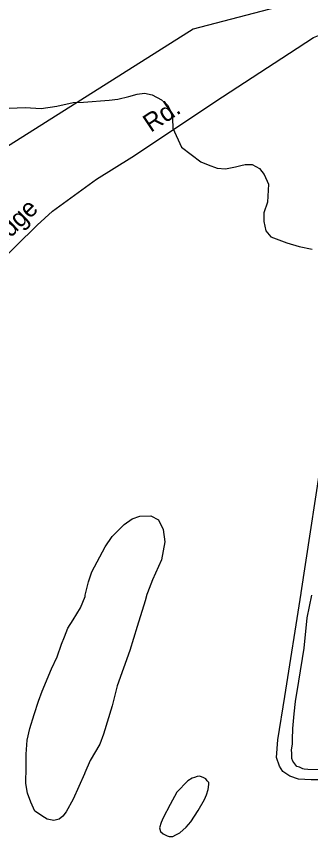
# Model space of a CAD drawing. Extents: x 2206922 to 2357709, y 510027 to 673830.
# Drawn here: x 2263859 to 2265398, y 591384 to 595671 of the extents above; entities that cross this region are included whole.
import ezdxf

# ---------------------------------------------------------------- set-up
doc = ezdxf.new("R2010")
doc.units = 0
for name, color, linetype in [('Exist Hydrographic Misc Water Feature', 7, 'Continuous'), ('Exist Road Non-System Type 51', 7, 'Continuous'), ('Exist Road Secondary Type 51 Attributed', 7, 'Continuous'), ('Exist Road Secondary Type 51 Label', 7, 'Continuous'), ('Exist Utilities Electrical Transmission Line', 7, 'Continuous')]:
    doc.layers.add(name, color=color, linetype=linetype)

msp = doc.modelspace()

# ---------------------------------------------------------------- linework, layer by layer
at = {"layer": 'Exist Hydrographic Misc Water Feature'}
for points in [[(2263820.5, 595191.7), (2263904.2, 595194.5), (2263988.5, 595189.5), (2264070.5, 595202.3), (2264156, 595221), (2264209.9, 595223.4), (2264343.6, 595232.5), (2264389.7, 595238.9), (2264447.6, 595251.7), (2264491.2, 595264.1), (2264529.2, 595270.2), (2264569.4, 595260.9), (2264617.8, 595235.3), (2264649.8, 595207.5), (2264670.3, 595167.8), (2264676.4, 595137.7), (2264677, 595087.8), (2264722.1, 594988.5), (2264824.5, 594911.4), (2264862.6, 594895.9), (2264908.5, 594878), (2264952.6, 594874.7), (2265004.5, 594885.1), (2265032.8, 594891.4), (2265056.4, 594897.6), (2265092.5, 594897.8), (2265131, 594876.1), (2265155, 594844.6), (2265177.4, 594794.9), (2265172.4, 594700.8), (2265152.7, 594644.6), (2265153.2, 594598.7), (2265164, 594550.8), (2265190.1, 594518.9), (2265274.1, 594488), (2265338.5, 594468.5), (2265406.4, 594455.1)], [(2264218.5, 592645.8), (2264235.8, 592715.8), (2264253.4, 592767.9), (2264324.1, 592898.8), (2264359.4, 592953), (2264422.6, 593016.1), (2264464.4, 593044.7), (2264504.2, 593059), (2264562.4, 593061.5), (2264602.6, 593039.7), (2264627, 592989.8), (2264635.8, 592925.6), (2264618.4, 592831.3), (2264571.2, 592726.8), (2264544.2, 592658.8), (2264542.1, 592648.9)], [(2264542.1, 592648.9), (2264532.5, 592616.7), (2264491.5, 592482.2), (2264452.9, 592357.8), (2264386.7, 592171.6), (2264359.8, 592067.3), (2264315.3, 591919.1), (2264295.4, 591866.9), (2264244.4, 591782.2), (2264216.7, 591718.2), (2264215.2, 591711.9), (2264156.4, 591579.7), (2264118.9, 591513.1), (2264101.2, 591491.1), (2264083.2, 591475.1), (2264055.3, 591468.8), (2264019.2, 591476.3), (2264005.3, 591484.1), (2263955.2, 591517.5), (2263934.7, 591563.6), (2263916.3, 591611.4), (2263907.7, 591661.4), (2263910.7, 591749.3), (2263910.3, 591815.1), (2263915.9, 591889.2), (2263928.8, 591949.4), (2263952.4, 592021.7), (2263973.9, 592091.8), (2263993, 592143.7), (2264041.8, 592260.4), (2264071.7, 592324.5), (2264094.5, 592390.8), (2264110.7, 592428.8), (2264127.7, 592472.9), (2264155.6, 592517), (2264194.9, 592579.6), (2264218.5, 592639.7), (2264218.5, 592645.8)], [(2265446, 591733.7), (2265384, 591734.9), (2265363.9, 591736.7), (2265358, 591738.8), (2265340.2, 591746.8), (2265326.4, 591750.5), (2265304.3, 591778.2), (2265299.8, 591792.2), (2265299.4, 591818.2), (2265297.7, 591838.3), (2265303, 591868.3), (2265302.8, 591892.3), (2265304.3, 591950), (2265311.5, 592026.1), (2265319.2, 592090.2), (2265336.1, 592196.3), (2265364.2, 592368.5), (2265380.8, 592528.6), (2265403.7, 592646.8)], [(2264853.8, 591602.3), (2264861.8, 591630.3), (2264865.3, 591656.2), (2264865.3, 591666.3), (2264857.1, 591676), (2264849.1, 591686.1), (2264839, 591692.1), (2264818.9, 591699.6), (2264805, 591697.7), (2264791, 591693.3), (2264778.9, 591689.4), (2264755.4, 591675.1), (2264697.5, 591616.5), (2264662.7, 591552.4), (2264627.2, 591482), (2264615.5, 591457.8), (2264607.3, 591429.8), (2264613.5, 591410.2), (2264626, 591398.2), (2264648.1, 591388.4), (2264658.2, 591384.4), (2264678, 591384.7), (2264693.4, 591392.9), (2264713.7, 591404.8), (2264747.4, 591433.4), (2264771.1, 591461.5), (2264810.5, 591521.6), (2264842.1, 591578.1), (2264853.8, 591602.3)]]:
    msp.add_lwpolyline(points, dxfattribs=at)
at = {"layer": 'Exist Road Non-System Type 51'}
for points in [[(2266084.2, 594239.7), (2266060.5, 594201.6), (2266044.7, 594181.4), (2266024.8, 594169.2), (2266004.9, 594165), (2265972.8, 594174.8), (2265892.4, 594226), (2265795.9, 594279), (2265739.7, 594296.5), (2265701.7, 594306.1), (2265665.7, 594303.8), (2265627.9, 594293.4), (2265604.2, 594267.3), (2265592.5, 594233.1), (2265571.5, 594127), (2265469.8, 593466.3), (2265347.4, 592657.7)], [(2267032.4, 591858.1), (2267020.5, 591831.9), (2267002.8, 591805.7), (2266983, 591787.5), (2266963.1, 591771.5), (2266931.3, 591763.2), (2266893.4, 591754.7), (2266571.7, 591733.9), (2265826.6, 591702.7), (2265598.8, 591690.8), (2265474.9, 591681.5), (2265400.9, 591680.8), (2265335, 591684.1), (2265288.7, 591699.8), (2265252.6, 591725.3), (2265234.4, 591753.3), (2265219.9, 591797), (2265227, 591891), (2265263, 592117.2), (2265347.8, 592655.9)]]:
    msp.add_lwpolyline(points, dxfattribs=at)
at = {"layer": 'Exist Road Secondary Type 51 Attributed'}
msp.add_lwpolyline([(2263627.3, 594246.6), (2263968.1, 594579.6), (2264047.4, 594652.4), (2264277.7, 594820.4), (2264462.4, 594936.2), (2264937.2, 595250.5), (2265286.9, 595479.7), (2265413.8, 595561.2), (2265473.6, 595585.1), (2265534.9, 595601.6), (2265612.7, 595624), (2265674, 595640.5), (2265759.2, 595669.6), (2265847.4, 595707), (2265937.1, 595763.9), (2266028.3, 595840.2), (2266098.6, 595907.5), (2266132.9, 595950.9), (2266139.7, 595959.2), (2266272.4, 596122.6), (2266412.5, 596345.8)], dxfattribs=at)
at = {"layer": 'Exist Utilities Electrical Transmission Line'}
msp.add_lwpolyline([(2266139.7, 595959.2), (2264784, 595604.9), (2261909.6, 593791.5)], dxfattribs=at)

# ---------------------------------------------------------------- texts
at = {"layer": 'Exist Road Secondary Type 51 Label'}
for s, rotation, p in [('Rd.', 33.5032, (2264561.7, 595062)), ('Bridge', 44.3372, (2263716.8, 594402.8))]:
    msp.add_text(s, height=95, rotation=rotation, dxfattribs=at).set_placement(p)

doc.saveas('drawing.dxf')
